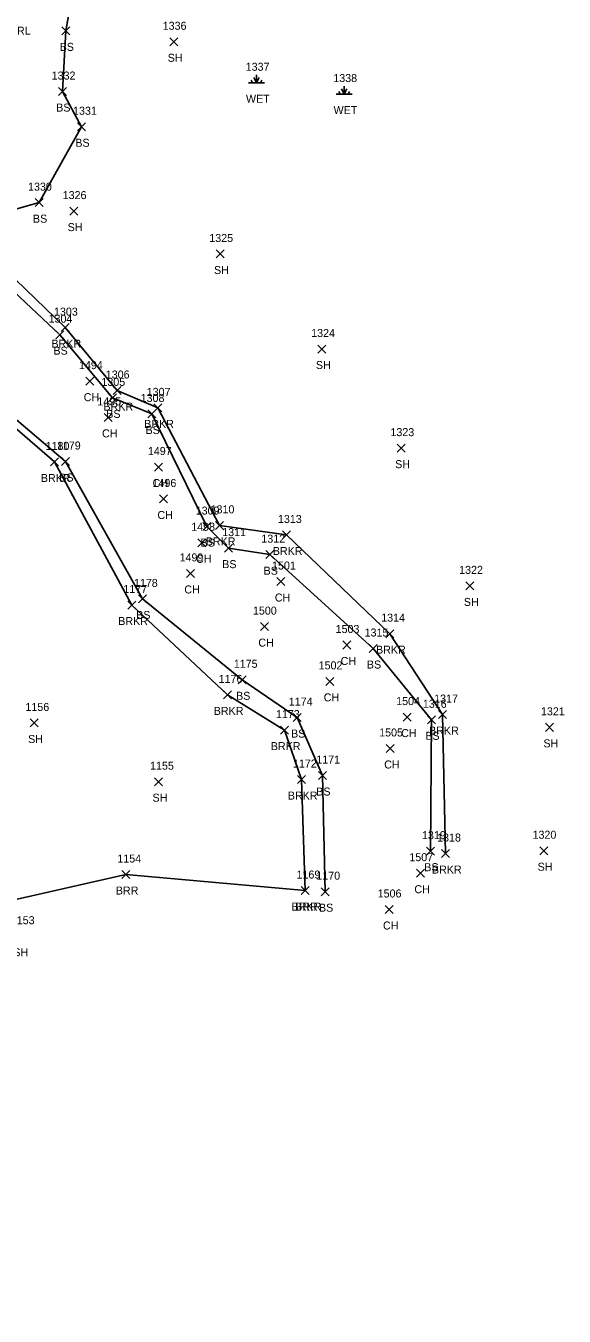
# Model space of a CAD drawing. Extents: x 1654425 to 1656893, y 667839 to 678429.
# Drawn here: x 1654644.4 to 1654779, y 668104.4 to 668426.8 of the extents above; entities that cross this region are included whole.
import ezdxf

# ---------------------------------------------------------------- set-up
doc = ezdxf.new("R2010")
doc.units = 0
for name, color, linetype in [('L_A', 7, 'Continuous'), ('L_I', 7, 'Continuous'), ('L_TIC', 7, 'Continuous'), ('LABL', 7, 'Continuous'), ('LAWE', 7, 'Continuous'), ('LELB', 7, 'Continuous'), ('LWET', 7, 'Continuous'), ('R_A', 7, 'Continuous')]:
    doc.layers.add(name, color=color, linetype=linetype)

msp = doc.modelspace()

# ---------------------------------------------------------------- linework, layer by layer
at = {"layer": 'L_TIC'}
for points in [[(1654653.39, 668424.58), (1654655.39, 668426.58)], [(1654655.39, 668424.58), (1654653.39, 668426.58)], [(1654680.35, 668421.85), (1654682.35, 668423.85)], [(1654682.35, 668421.85), (1654680.35, 668423.85)], [(1654652.52, 668409.41), (1654654.52, 668411.41)], [(1654654.52, 668409.41), (1654652.52, 668411.41)], [(1654657.31, 668400.62), (1654659.31, 668402.62)], [(1654659.31, 668400.62), (1654657.31, 668402.62)], [(1654646.7, 668381.66), (1654648.7, 668383.66)], [(1654648.7, 668381.66), (1654646.7, 668383.66)], [(1654655.33, 668379.55), (1654657.33, 668381.55)], [(1654657.33, 668379.55), (1654655.33, 668381.55)], [(1654691.94, 668368.83), (1654693.94, 668370.83)], [(1654693.94, 668368.83), (1654691.94, 668370.83)], [(1654651.83, 668348.67), (1654653.83, 668350.67)], [(1654653.83, 668348.67), (1654651.83, 668350.67)], [(1654653.18, 668350.43), (1654655.18, 668352.43)], [(1654655.18, 668350.43), (1654653.18, 668352.43)], [(1654717.42, 668345.09), (1654719.42, 668347.09)], [(1654719.42, 668345.09), (1654717.42, 668347.09)], [(1654659.36, 668337.06), (1654661.36, 668339.06)], [(1654661.36, 668337.06), (1654659.36, 668339.06)], [(1654665.04, 668332.88), (1654667.04, 668334.88)], [(1654667.04, 668332.88), (1654665.04, 668334.88)], [(1654666.19, 668334.72), (1654668.19, 668336.72)], [(1654668.19, 668334.72), (1654666.19, 668336.72)], [(1654674.85, 668328.86), (1654676.85, 668330.86)], [(1654676.85, 668328.86), (1654674.85, 668330.86)], [(1654676.37, 668330.39), (1654678.37, 668332.39)], [(1654678.37, 668330.39), (1654676.37, 668332.39)], [(1654663.94, 668328.01), (1654665.94, 668330.01)], [(1654665.94, 668328.01), (1654663.94, 668330.01)], [(1654737.24, 668320.32), (1654739.24, 668322.32)], [(1654739.24, 668320.32), (1654737.24, 668322.32)], [(1654650.53, 668316.87), (1654652.53, 668318.87)], [(1654652.53, 668316.87), (1654650.53, 668318.87)], [(1654653.27, 668316.98), (1654655.27, 668318.98)], [(1654655.27, 668316.98), (1654653.27, 668318.98)], [(1654676.58, 668315.6), (1654678.58, 668317.6)], [(1654678.58, 668315.6), (1654676.58, 668317.6)], [(1654677.79, 668307.62), (1654679.79, 668309.62)], [(1654679.79, 668307.62), (1654677.79, 668309.62)], [(1654688.63, 668300.72), (1654690.63, 668302.72)], [(1654690.63, 668300.72), (1654688.63, 668302.72)], [(1654691.78, 668301.03), (1654693.78, 668303.03)], [(1654693.78, 668301.03), (1654691.78, 668303.03)], [(1654687.42, 668296.67), (1654689.42, 668298.67)], [(1654689.42, 668296.67), (1654687.42, 668298.67)], [(1654708.54, 668298.63), (1654710.54, 668300.63)], [(1654710.54, 668298.63), (1654708.54, 668300.63)], [(1654694.03, 668295.34), (1654696.03, 668297.34)], [(1654696.03, 668295.34), (1654694.03, 668297.34)], [(1654704.38, 668293.71), (1654706.38, 668295.71)], [(1654706.38, 668293.71), (1654704.38, 668295.71)], [(1654684.51, 668289.02), (1654686.51, 668291.02)], [(1654686.51, 668289.02), (1654684.51, 668291.02)], [(1654707.15, 668287), (1654709.15, 668289)], [(1654709.15, 668287), (1654707.15, 668289)], [(1654754.42, 668285.91), (1654756.42, 668287.91)], [(1654756.42, 668285.91), (1654754.42, 668287.91)], [(1654669.88, 668281.13), (1654671.88, 668283.13)], [(1654671.88, 668281.13), (1654669.88, 668283.13)], [(1654672.53, 668282.65), (1654674.53, 668284.65)], [(1654674.53, 668282.65), (1654672.53, 668284.65)], [(1654703.02, 668275.73), (1654705.02, 668277.73)], [(1654705.02, 668275.73), (1654703.02, 668277.73)], [(1654734.36, 668273.97), (1654736.36, 668275.97)], [(1654736.36, 668273.97), (1654734.36, 668275.97)], [(1654723.62, 668271.14), (1654725.62, 668273.14)], [(1654725.62, 668271.14), (1654723.62, 668273.14)], [(1654730.22, 668270.26), (1654732.22, 668272.26)], [(1654732.22, 668270.26), (1654730.22, 668272.26)], [(1654697.51, 668262.45), (1654699.51, 668264.45)], [(1654699.51, 668262.45), (1654697.51, 668264.45)], [(1654719.37, 668262.05), (1654721.37, 668264.05)], [(1654721.37, 668262.05), (1654719.37, 668264.05)], [(1654693.77, 668258.68), (1654695.77, 668260.68)], [(1654695.77, 668258.68), (1654693.77, 668260.68)], [(1654645.45, 668251.66), (1654647.45, 668253.66)], [(1654647.45, 668251.66), (1654645.45, 668253.66)], [(1654711.25, 668253.01), (1654713.25, 668255.01)], [(1654713.25, 668253.01), (1654711.25, 668255.01)], [(1654738.75, 668253.13), (1654740.75, 668255.13)], [(1654740.75, 668253.13), (1654738.75, 668255.13)], [(1654744.83, 668252.45), (1654746.83, 668254.45)], [(1654746.83, 668252.45), (1654744.83, 668254.45)], [(1654747.61, 668253.76), (1654749.61, 668255.76)], [(1654749.61, 668253.76), (1654747.61, 668255.76)], [(1654708.04, 668249.88), (1654710.04, 668251.88)], [(1654710.04, 668249.88), (1654708.04, 668251.88)], [(1654774.32, 668250.57), (1654776.32, 668252.57)], [(1654776.32, 668250.57), (1654774.32, 668252.57)], [(1654734.5, 668245.29), (1654736.5, 668247.29)], [(1654736.5, 668245.29), (1654734.5, 668247.29)], [(1654717.56, 668238.52), (1654719.56, 668240.52)], [(1654719.56, 668238.52), (1654717.56, 668240.52)], [(1654676.56, 668236.99), (1654678.56, 668238.99)], [(1654678.56, 668236.99), (1654676.56, 668238.99)], [(1654712.3, 668237.52), (1654714.3, 668239.52)], [(1654714.3, 668237.52), (1654712.3, 668239.52)], [(1654744.57, 668219.63), (1654746.57, 668221.63)], [(1654746.57, 668219.63), (1654744.57, 668221.63)], [(1654772.87, 668219.74), (1654774.87, 668221.74)], [(1654774.87, 668219.74), (1654772.87, 668221.74)], [(1654748.34, 668219.04), (1654750.34, 668221.04)], [(1654750.34, 668219.04), (1654748.34, 668221.04)], [(1654668.38, 668213.79), (1654670.38, 668215.79)], [(1654670.38, 668213.79), (1654668.38, 668215.79)], [(1654742.06, 668214.13), (1654744.06, 668216.13)], [(1654744.06, 668214.13), (1654742.06, 668216.13)], [(1654713.24, 668209.79), (1654715.24, 668211.79)], [(1654715.24, 668209.79), (1654713.24, 668211.79)], [(1654713.24, 668209.79), (1654715.24, 668211.79)], [(1654715.24, 668209.79), (1654713.24, 668211.79)], [(1654718.24, 668209.51), (1654720.24, 668211.51)], [(1654720.24, 668209.51), (1654718.24, 668211.51)], [(1654734.19, 668205.06), (1654736.19, 668207.06)], [(1654736.19, 668205.06), (1654734.19, 668207.06)]]:
    msp.add_lwpolyline(points, dxfattribs=at)
at = {"layer": 'LABL'}
msp.add_lwpolyline([(1654605, 668046.16), (1654594.45, 668068.9), (1654587.86, 668115.59), (1654591.34, 668138.45), (1654594.61, 668153.33), (1654611.07, 668168.74), (1654623.05, 668204.29), (1654669.38, 668214.79), (1654714.24, 668210.79)], dxfattribs=at)
at = {"layer": 'LAWE'}
for points in [[(1654631.34, 668375.97), (1654634.24, 668370.63), (1654654.18, 668351.43), (1654667.19, 668335.72), (1654677.37, 668331.39), (1654692.78, 668302.03), (1654709.54, 668299.63), (1654735.36, 668274.97), (1654748.61, 668254.76), (1654749.34, 668220.04)], [(1654714.24, 668210.79), (1654713.3, 668238.52), (1654709.04, 668250.88), (1654694.77, 668259.68), (1654670.88, 668282.13), (1654651.53, 668317.87), (1654632.31, 668334.51), (1654624.24, 668336.73)]]:
    msp.add_lwpolyline(points, dxfattribs=at)
at = {"layer": 'LELB'}
for points in [[(1654632.09, 668378.26), (1654647.7, 668382.66), (1654658.31, 668401.62), (1654653.52, 668410.41), (1654654.39, 668425.58), (1654665.51, 668489.09), (1654668.15, 668504.58), (1654668.74, 668510.32), (1654667.06, 668546.44)], [(1654630.8, 668375.77), (1654632.76, 668368.43), (1654652.83, 668349.67), (1654666.04, 668333.88), (1654675.85, 668329.86), (1654689.63, 668301.72), (1654695.03, 668296.34), (1654705.38, 668294.71), (1654731.22, 668271.26), (1654745.83, 668253.45), (1654745.57, 668220.63)], [(1654719.24, 668210.51), (1654718.56, 668239.52), (1654712.25, 668254.01), (1654698.51, 668263.45), (1654673.53, 668283.65), (1654654.27, 668317.98), (1654633.02, 668335.94), (1654624.64, 668338.82), (1654619.07, 668342.23), (1654579.05, 668354.59), (1654565.49, 668358.45), (1654562.65, 668358.71), (1654535.4, 668369.35)]]:
    msp.add_lwpolyline(points, dxfattribs=at)
at = {"layer": 'LWET'}
for p, q in [((1654702.05, 668412.61), (1654702.05, 668414.61)), ((1654704.05, 668412.61), (1654700.05, 668412.61)), ((1654701.05, 668412.61), (1654700.71, 668413.28)), ((1654702.05, 668412.61), (1654701.38, 668413.94)), ((1654702.05, 668412.61), (1654702.71, 668413.94)), ((1654703.05, 668412.61), (1654703.38, 668413.28)), ((1654723.95, 668409.79), (1654723.95, 668411.79)), ((1654725.95, 668409.79), (1654721.95, 668409.79)), ((1654722.95, 668409.79), (1654722.62, 668410.46)), ((1654723.95, 668409.79), (1654723.29, 668411.12)), ((1654723.95, 668409.79), (1654724.62, 668411.12)), ((1654724.95, 668409.79), (1654725.29, 668410.46))]:
    msp.add_line(p, q, dxfattribs=at)

# ---------------------------------------------------------------- texts
at = {"layer": 'L_A'}
for s, p in [('BS', (1654652.83, 668420.58)), ('SH', (1654679.84, 668417.85)), ('WET', (1654699.42, 668407.61)), ('BS', (1654651.96, 668405.41)), ('WET', (1654721.33, 668404.79)), ('BS', (1654656.75, 668396.62)), ('BS', (1654646.14, 668377.66)), ('SH', (1654654.82, 668375.55)), ('SH', (1654691.43, 668364.83)), ('BRKR', (1654650.77, 668346.43)), ('BS', (1654651.27, 668344.67)), ('SH', (1654716.91, 668341.09)), ('CH', (1654658.84, 668333.06)), ('BRKR', (1654663.78, 668330.72)), ('BS', (1654664.48, 668328.88)), ('BRKR', (1654673.96, 668326.39)), ('CH', (1654663.43, 668324.01)), ('BS', (1654674.3, 668324.86)), ('SH', (1654736.73, 668316.32)), ('BRKR', (1654648.12, 668312.87)), ('BS', (1654652.72, 668312.98)), ('CH', (1654676.07, 668311.6)), ('CH', (1654677.28, 668303.62)), ('BS', (1654688.07, 668296.72)), ('BRKR', (1654689.37, 668297.03)), ('BRKR', (1654706.13, 668294.63)), ('CH', (1654686.91, 668292.67)), ('BS', (1654693.48, 668291.34)), ('BS', (1654703.83, 668289.71)), ('CH', (1654684, 668285.02)), ('CH', (1654706.64, 668283)), ('SH', (1654753.91, 668281.91)), ('BS', (1654671.97, 668278.65)), ('BRKR', (1654667.47, 668277.13)), ('CH', (1654702.51, 668271.73)), ('BRKR', (1654731.95, 668269.97)), ('CH', (1654723.1, 668267.14)), ('BS', (1654729.66, 668266.26)), ('BS', (1654696.95, 668258.45)), ('CH', (1654718.86, 668258.05)), ('BRKR', (1654691.36, 668254.68)), ('BS', (1654710.7, 668249.01)), ('CH', (1654738.24, 668249.13)), ('BS', (1654744.27, 668248.45)), ('BRKR', (1654745.2, 668249.76)), ('SH', (1654644.94, 668247.66)), ('BRKR', (1654705.63, 668245.88)), ('SH', (1654773.8, 668246.57)), ('CH', (1654733.99, 668241.29)), ('SH', (1654676.05, 668232.99)), ('BRKR', (1654709.89, 668233.52)), ('BS', (1654717, 668234.52)), ('BS', (1654744.01, 668215.63)), ('BRKR', (1654745.93, 668215.04)), ('SH', (1654772.35, 668215.74)), ('BRR', (1654666.87, 668209.79)), ('CH', (1654741.54, 668210.13)), ('BRKR', (1654710.83, 668205.79)), ('BRR', (1654711.73, 668205.79)), ('BS', (1654717.68, 668205.51)), ('CH', (1654733.68, 668201.06)), ('SH', (1654641.23, 668194.38))]:
    msp.add_text(s, height=2, dxfattribs=at).set_placement(p)
at = {"layer": 'L_I'}
for s, p in [('1336', (1654678.6, 668425.85)), ('1332', (1654650.83, 668413.41)), ('1337', (1654699.35, 668415.61)), ('1338', (1654721.26, 668412.79)), ('1331', (1654656.18, 668404.62)), ('1330', (1654644.92, 668385.66)), ('1326', (1654653.58, 668383.55)), ('1325', (1654690.25, 668372.83)), ('1304', (1654650.06, 668352.67)), ('1303', (1654651.41, 668354.43)), ('1324', (1654715.73, 668349.09)), ('1494', (1654657.66, 668341.06)), ('1306', (1654664.36, 668338.72)), ('1305', (1654663.27, 668336.88)), ('1495', (1654662.25, 668332.01)), ('1308', (1654673.08, 668332.86)), ('1307', (1654674.6, 668334.39)), ('1323', (1654735.55, 668324.32)), ('1180', (1654649.32, 668320.87)), ('1179', (1654652.14, 668320.98)), ('1497', (1654674.89, 668319.6)), ('1496', (1654676.05, 668311.62)), ('1309', (1654686.85, 668304.72)), ('1310', (1654690.57, 668305.03)), ('1498', (1654685.73, 668300.67)), ('1313', (1654707.42, 668302.63)), ('1311', (1654693.48, 668299.34)), ('1312', (1654703.26, 668297.71)), ('1499', (1654682.81, 668293.02)), ('1501', (1654705.94, 668291)), ('1322', (1654752.73, 668289.91)), ('1177', (1654668.76, 668285.13)), ('1178', (1654671.4, 668286.65)), ('1500', (1654701.16, 668279.73)), ('1314', (1654733.24, 668277.97)), ('1503', (1654721.84, 668275.14)), ('1315', (1654729.09, 668274.26)), ('1175', (1654696.38, 668266.45)), ('1502', (1654717.6, 668266.05)), ('1176', (1654692.59, 668262.68)), ('1156', (1654644.27, 668255.66)), ('1174', (1654710.13, 668257.01)), ('1504', (1654736.98, 668257.13)), ('1316', (1654743.65, 668256.45)), ('1317', (1654746.48, 668257.76)), ('1173', (1654706.92, 668253.88)), ('1321', (1654773.19, 668254.57)), ('1505', (1654732.73, 668249.29)), ('1171', (1654717, 668242.52)), ('1155', (1654675.44, 668240.99)), ('1172', (1654711.17, 668241.52)), ('1319', (1654743.44, 668223.63)), ('1318', (1654747.22, 668223.04)), ('1320', (1654771.09, 668223.74)), ('1154', (1654667.26, 668217.79)), ('1507', (1654740.28, 668218.13)), ('1169', (1654712.06, 668213.79)), ('1169', (1654712.06, 668213.79)), ('1170', (1654717.03, 668213.51)), ('1506', (1654732.36, 668209.06)), ('1153', (1654640.61, 668202.38))]:
    msp.add_text(s, height=2, dxfattribs=at).set_placement(p)
at = {"layer": 'R_A'}
msp.add_text('GRL', height=2, dxfattribs=at).set_placement((1654640.07, 668424.62))

doc.saveas('drawing.dxf')
